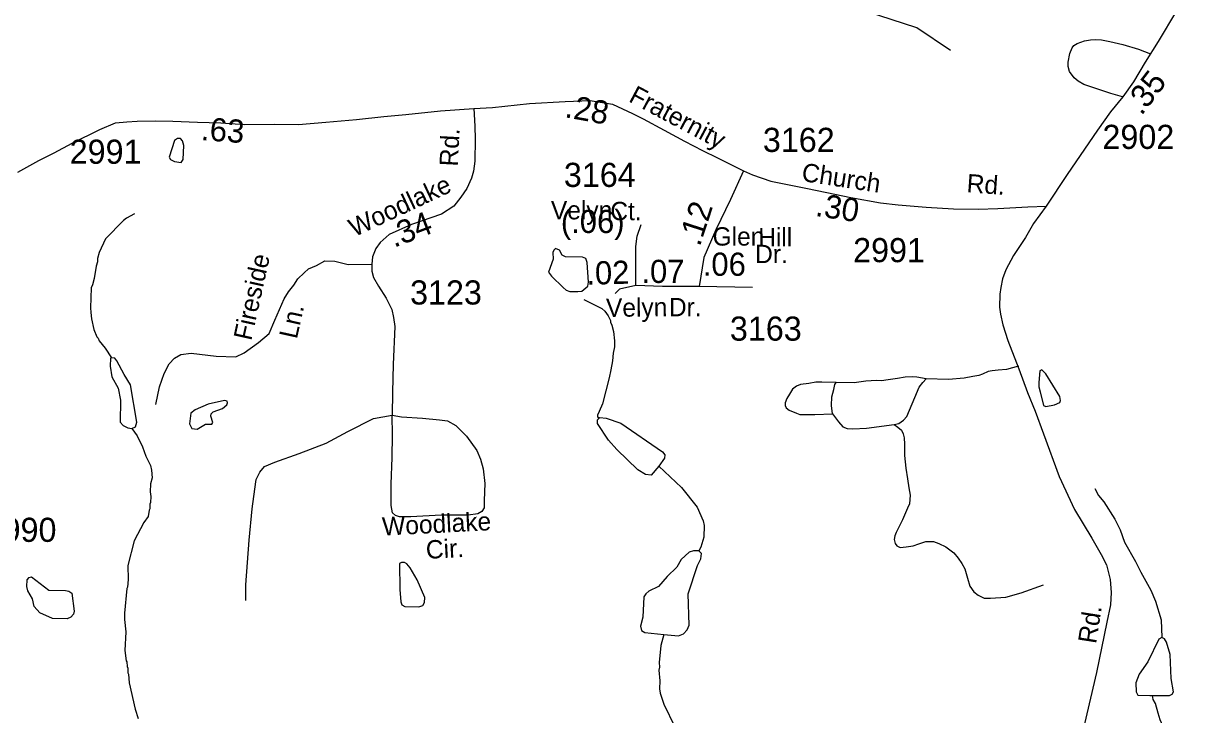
# Model space of a CAD drawing. Extents: x 1547597 to 1699558, y 810033 to 920809.
# Drawn here: x 1609618 to 1615688, y 824418 to 827999 of the extents above; entities that cross this region are included whole.
import ezdxf

# ---------------------------------------------------------------- set-up
doc = ezdxf.new("R2010")
doc.units = 0
for name, color, linetype in [('Exist Hydrographic Creek Single Shore', 7, 'Continuous'), ('Exist Hydrographic Misc Water Feature', 7, 'Continuous'), ('Exist Road Non-System Type 51', 7, 'Continuous'), ('Exist Road Non-System Type 51 Label', 7, 'Continuous'), ('Exist Road Secondary Mileage Hundredths English Label', 7, 'Continuous'), ('Exist Road Secondary Type 51 Attributed', 7, 'Continuous'), ('Exist Road Secondary Type 51 Label', 7, 'Continuous'), ('Exist Road Secondary Type 51 Number Label', 7, 'Continuous')]:
    doc.layers.add(name, color=color, linetype=linetype)

msp = doc.modelspace()

# ---------------------------------------------------------------- linework, layer by layer
at = {"layer": 'Exist Hydrographic Creek Single Shore'}
msp.add_lwpolyline([(1614418.7, 827857.8), (1614244.7, 827976.2), (1613920.7, 828081.3), (1613280.7, 828215.7), (1612876.7, 828552.1), (1612271.7, 828810.6), (1612074.7, 829021.4), (1611787.7, 829391.6), (1611415.7, 829665), (1611042.6, 829820.4), (1610759.7, 829865.5), (1610619.7, 829934), (1610330.7, 830205.7), (1610132.7, 830308.2), (1609659.7, 830472.1)], dxfattribs=at)
at = {"layer": 'Exist Hydrographic Misc Water Feature'}
for points in [[(1610448.8, 827365.8), (1610442.1, 827390), (1610431.1, 827402.6), (1610415.4, 827403.3), (1610400.9, 827392.8), (1610372.6, 827306.5), (1610379.9, 827293.4), (1610399.7, 827283), (1610434.4, 827278), (1610445.6, 827294.1), (1610448.8, 827365.8)], [(1610193, 827011.4), (1610150.8, 826990), (1610136.6, 826978.2), (1610043.4, 826883.5), (1610010.4, 826812), (1610002, 826780.2), (1610001.8, 826764.2), (1609993.5, 826740.3), (1609984.6, 826676.4), (1609976.2, 826644.6), (1609968, 826628.7), (1609964.6, 826524.7), (1609966.2, 826500.7), (1609969.8, 826468.7), (1609983, 826412.5), (1609998.5, 826374.3), (1610004.4, 826368.2), (1610010.2, 826354.2), (1610041.7, 826315.7), (1610073, 826266.8)], [(1612412.2, 826630.3), (1612429.1, 826616.3), (1612448.3, 826609.4), (1612488.6, 826609.5), (1612509.6, 826612.1), (1612540.1, 826638.2), (1612543.6, 826658.6), (1612537.1, 826759.6), (1612530.1, 826780.1), (1612513.1, 826788), (1612425.5, 826790.1), (1612408.5, 826798), (1612393.3, 826824.1), (1612374.1, 826832.1), (1612364.1, 826823.9), (1612360.1, 826811.3), (1612360.8, 826778.2), (1612336.9, 826710.6), (1612352.1, 826689.4), (1612412.2, 826630.3)], [(1612519.6, 826569.1), (1612612.9, 826521.8), (1612628.7, 826507.6), (1612646.4, 826483.3), (1612658, 826459.2), (1612657.9, 826451.2), (1612665.7, 826435.1), (1612673.3, 826403), (1612678.7, 826354.9), (1612678.2, 826322.9), (1612671.8, 826291.1), (1612669.2, 826251.1), (1612660.6, 826203.2), (1612652, 826163.4), (1612616.2, 826027.9), (1612599.7, 825988.1), (1612591.3, 825968.3), (1612591.2, 825960), (1612597.3, 825951.1)], [(1610073, 826266.8), (1610067.8, 826264.9), (1610066.7, 826223.4), (1610075.2, 826167.8), (1610108.3, 826108.3), (1610121, 826047), (1610119.1, 825933.7), (1610133.7, 825916), (1610158.2, 825903.1), (1610179, 825900.6)], [(1610179, 825900.6), (1610198.2, 825909), (1610204.1, 825932.1), (1610172.5, 826126.5), (1610138.7, 826180.4), (1610101.5, 826251.1), (1610091.1, 826263.9), (1610073, 826266.8)], [(1614883.3, 826090.7), (1614901.3, 826018.7), (1614912.1, 826014.1), (1614957, 826023.4), (1614984.5, 826034.8), (1614988.2, 826044.6), (1614985.3, 826065.7), (1614912.1, 826184.1), (1614891.7, 826204.6), (1614881.3, 826198.8), (1614875.8, 826139.2), (1614875.9, 826115.9), (1614883.3, 826090.7)], [(1610574.2, 826025.7), (1610506.7, 825996.3), (1610485.1, 825979.6), (1610477.7, 825924.9), (1610490.6, 825900.1), (1610517.1, 825897), (1610559.8, 825922.2), (1610592.7, 825922.7), (1610598.2, 825930.9), (1610587.6, 825964.3), (1610590, 825975.7), (1610600.2, 825987), (1610649.3, 826003.8), (1610670.4, 826023.2), (1610675.1, 826033.2), (1610672.4, 826041), (1610658.8, 826045.2), (1610574.2, 826025.7)], [(1612908.3, 825704.6), (1612868.3, 825657.6), (1612839.4, 825662.4), (1612799.2, 825686.5), (1612691.6, 825790.5), (1612648.2, 825840.1), (1612590.4, 825925.1), (1612590.6, 825944.5), (1612597.3, 825951.1)], [(1612597.3, 825951.1), (1612603, 825956.6), (1612636.3, 825953.6), (1612711.5, 825927.3), (1612926.7, 825779.9), (1612938.8, 825764), (1612938.6, 825745.6), (1612908.3, 825704.6)], [(1610179, 825900.6), (1610207.4, 825861.5), (1610234.5, 825805.1), (1610251.9, 825756.9), (1610275.2, 825708.6), (1610280.9, 825684.5), (1610284.4, 825644.5), (1610276, 825612.6), (1610273.4, 825572.7), (1610277.1, 825548.6), (1610276.6, 825516.6), (1610272.5, 825508.7), (1610272.2, 825484.7), (1610268.1, 825476.7), (1610263.7, 825444.8), (1610241.2, 825413.1), (1610192, 825317.9), (1610158.3, 825190.3), (1610159.3, 825118.4), (1610156.7, 825078.4), (1610152.6, 825070.5), (1610140.8, 824942.6), (1610140.4, 824910.6), (1610147.5, 824846.6), (1610142.3, 824750.7), (1610149.4, 824696.6), (1610153.4, 824690.5), (1610155.1, 824666.5), (1610159, 824658.5), (1610158.7, 824634.5), (1610162.6, 824626.4), (1610165.9, 824582.4), (1610196.1, 824446), (1610211.4, 824397.8)], [(1612908.3, 825704.6), (1613025.6, 825594.4), (1613107.8, 825492.4), (1613138.7, 825421.8), (1613143.7, 825398), (1613142.2, 825337.5), (1613126.7, 825285.8), (1613115, 825265.8)], [(1615166.7, 825589.1), (1615186.2, 825552.1), (1615213.7, 825519.7), (1615270.5, 825431), (1615297.7, 825374.6), (1615320.9, 825310.3), (1615376.9, 825211.5), (1615404.1, 825156.5)], [(1613115, 825265.8), (1613087.8, 825267), (1613065, 825258.5), (1613025, 825221.1), (1613000.9, 825181), (1612951.3, 825134.1), (1612905.9, 825082), (1612856.4, 825057.9), (1612841.4, 825044), (1612830.7, 825028.3), (1612826.1, 824923), (1612814.1, 824876.6), (1612818.3, 824853.7), (1612835.7, 824843), (1612934.2, 824833.5)], [(1612934.2, 824833.5), (1613011, 824826.1), (1613036.7, 824836.3), (1613055.2, 824856.3), (1613066.1, 824881.7), (1613060, 825043.3), (1613108, 825189.5), (1613126, 825224.4), (1613129, 825251.6), (1613115, 825265.8)], [(1611657.7, 825116.5), (1611621.1, 825177.5), (1611603.3, 825198.1), (1611591.7, 825206.4), (1611574.9, 825206.6), (1611566, 825201.4), (1611566.4, 825066.2), (1611572, 825001.5), (1611577.7, 824986.9), (1611592.2, 824978), (1611666.1, 824976), (1611685.9, 824982.8), (1611694.8, 824998.4), (1611695.7, 825024.6), (1611657.7, 825116.5)], [(1609767.9, 824916), (1609703, 824944.5), (1609673.5, 824977.4), (1609664.2, 825017.8), (1609640.4, 825059.8), (1609635.8, 825081.3), (1609636.2, 825116.8), (1609646.7, 825128.5), (1609659.9, 825131.8), (1609749.4, 825062), (1609835.4, 825060.3), (1609852.7, 825057.4), (1609868.6, 825046.1), (1609880.8, 824954.3), (1609876.4, 824937.7), (1609863.1, 824923.2), (1609844.2, 824913.7), (1609767.9, 824916)], [(1615404.1, 825156.5), (1615456.8, 825062.6), (1615480.7, 825005.2), (1615510.9, 824908.2), (1615514, 824816.9)], [(1612934.2, 824833.5), (1612919, 824776), (1612909.7, 824688.1), (1612911.4, 824664.1), (1612909.2, 824648.1), (1612914.5, 824592), (1612911.9, 824552.1), (1612915.6, 824528.1), (1612934.8, 824471.8), (1612991.2, 824355.1), (1613014.6, 824314.7), (1613070.7, 824178), (1613103.8, 824117.5), (1613115.4, 824085.4), (1613162.1, 823992.7), (1613191.1, 823920.3), (1613206.5, 823872.2), (1613217.7, 823824), (1613221.3, 823792), (1613225.2, 823783.9), (1613224.6, 823735.9), (1613239.6, 823663.8), (1613241.5, 823605.4)], [(1615514, 824816.9), (1615498.6, 824807.9), (1615440.8, 824691.4), (1615396.6, 824626.6), (1615379.8, 824582.5), (1615380, 824536.2), (1615389.3, 824519.1), (1615451.2, 824517.2), (1615464.6, 824517.2)], [(1615464.6, 824517.2), (1615553.9, 824516.6), (1615566.3, 824523.2), (1615574.6, 824536.1), (1615562.4, 824605), (1615556.3, 824729.6), (1615537.2, 824792.5), (1615527.2, 824809.6), (1615514, 824816.9)], [(1615494.3, 824424.5), (1615480, 824475.6), (1615468, 824496.7), (1615464.6, 824517.2)], [(1615297.7, 823552.8), (1615323.5, 823602.7), (1615331.6, 823610.6), (1615360.2, 823658.2), (1615380.5, 823681.9), (1615392.8, 823705.7), (1615498.7, 823848.2), (1615531.5, 823911.7), (1615535.9, 823927.7), (1615533.9, 823935.7), (1615540.1, 823943.6), (1615557.2, 824031.3), (1615572, 824091.1), (1615576.2, 824107), (1615576.9, 824155), (1615569.7, 824211.1), (1615550.5, 824275.4), (1615538.9, 824299.5), (1615523.5, 824347.7), (1615504.4, 824390.3), (1615494.3, 824424.5)]]:
    msp.add_lwpolyline(points, dxfattribs=at)
at = {"layer": 'Exist Road Non-System Type 51'}
for points in [[(1615310.7, 827617.8), (1615249.6, 827635), (1615110.3, 827682.6), (1615079.8, 827699.8), (1615059, 827717.3), (1615035.4, 827749.6), (1615028.1, 827774.9), (1615028, 827797.8), (1615036.5, 827843.6), (1615049.3, 827872.2), (1615058.5, 827883.8), (1615075.2, 827895), (1615113.3, 827908.5), (1615144.4, 827913.9), (1615169.2, 827915.8), (1615201.8, 827913.3), (1615245.1, 827904.8), (1615310.8, 827890.1), (1615392.3, 827865), (1615454.3, 827840.6)], [(1610302.5, 826024.8), (1610321.6, 826116.4), (1610346.6, 826184.2), (1610373, 826235.7), (1610399.4, 826265.3), (1610433.6, 826282.8), (1610485.6, 826290.2), (1610615.3, 826275.1), (1610717, 826271.2), (1610760.8, 826291.7), (1610834.5, 826345.9), (1610890, 826391.6), (1610920.2, 826461.4), (1610968.1, 826572.3), (1610990.1, 826607.5), (1611017.5, 826643.1), (1611038.1, 826675.5), (1611072.3, 826707), (1611093.8, 826726.7), (1611134.9, 826744.5), (1611179, 826768.3), (1611231.1, 826766.9), (1611299.5, 826750.4), (1611421.6, 826750.9)], [(1614770.8, 826223.8), (1614709.8, 826206.1), (1614665.1, 826202.1), (1614634.8, 826199.4), (1614613.3, 826194.7), (1614584.4, 826181.3), (1614566.4, 826174.8), (1614534.2, 826168.6), (1614489.5, 826161), (1614409.2, 826154.5), (1614293.6, 826158)], [(1614293.6, 826158), (1614244, 826166.6), (1614222.7, 826167.2), (1614183.5, 826166.6), (1614144.1, 826158.9), (1614095.8, 826151.4), (1614061.8, 826147.1), (1614035.2, 826147.9), (1613979.9, 826146), (1613920.9, 826137.1), (1613826.6, 826138.1)], [(1614128, 825920.7), (1614151.3, 825925.4), (1614175, 825942.5), (1614193.3, 825961.5), (1614206.8, 825994.9), (1614233.7, 826060), (1614256.7, 826114.6), (1614275.2, 826138.9), (1614293.6, 826158)], [(1613826.6, 826138.1), (1613751.9, 826140.4), (1613721.6, 826139.5), (1613685.8, 826133.5), (1613642.9, 826127.6), (1613621.3, 826119.4), (1613601.3, 826103.9), (1613584.5, 826077.7), (1613571.4, 826054.9), (1613563.6, 826033.8), (1613563.2, 826019.6), (1613568.1, 826007), (1613583.8, 825995.8), (1613620.7, 825978.7), (1613638.3, 825972.8), (1613661.4, 825972.1), (1613716.6, 825972.2), (1613807.5, 825976.6)], [(1613807.5, 825976.6), (1613803.5, 826019.5), (1613804.8, 826064), (1613814.9, 826102.9), (1613819.2, 826127.7), (1613826.6, 826138.1)], [(1610768.8, 825009.3), (1610769.8, 825089.4), (1610786.7, 825321), (1610802.8, 825484.7), (1610816.1, 825586.5), (1610822.7, 825636.4), (1610841.3, 825674), (1610865.7, 825703.8), (1610919.8, 825725.1), (1611046.2, 825771.3), (1611184.7, 825823.6), (1611297.4, 825884.1), (1611430.2, 825952.5), (1611528.2, 825969.1)], [(1611528.2, 825969.1), (1611576.1, 825960.5), (1611683.8, 825953.1), (1611771.7, 825944.1), (1611813.6, 825939.5), (1611857.1, 825915), (1611912.4, 825860.4), (1611965.3, 825785.7), (1611984.9, 825741.5), (1611998, 825691.4), (1612007.1, 825615.2), (1612003.9, 825527.4), (1612003.6, 825489.4), (1611991.1, 825469.6), (1611971.1, 825457.8), (1611921.1, 825450.4), (1611781.2, 825450.3), (1611623.4, 825442.3), (1611565.4, 825443), (1611545.1, 825449.4), (1611529.8, 825463.4), (1611522.1, 825501.5), (1611521.6, 825611.4), (1611527.4, 825749.4), (1611528.9, 825865.2), (1611528.2, 825969.1)], [(1613807.5, 825976.6), (1613838.3, 825934.7), (1613860.7, 825909.1), (1613883.5, 825899.5), (1613913.8, 825898.6), (1613983.3, 825901.9), (1614128, 825920.7)], [(1614128, 825920.7), (1614145.5, 825907.7), (1614164.5, 825891.1), (1614174.7, 825873), (1614179.4, 825851.5), (1614180.2, 825819.4), (1614180.2, 825760.6), (1614187.1, 825694.5), (1614196.2, 825639.4), (1614203.7, 825592.9), (1614209.7, 825555.3), (1614209, 825532.1), (1614206.5, 825509.1), (1614197, 825488), (1614170.2, 825426.4), (1614151.3, 825389.6), (1614138, 825361.5), (1614130.3, 825343.9), (1614128, 825324.4), (1614132.7, 825304.7), (1614141.2, 825291.9), (1614158.8, 825284.3), (1614189.2, 825286.9), (1614224.9, 825293), (1614255.5, 825302.8), (1614291.4, 825314.2), (1614330.6, 825314.8), (1614358.8, 825305), (1614395.6, 825286.1), (1614435.6, 825255.7), (1614458, 825228.3), (1614478.5, 825201), (1614493.7, 825173.8), (1614506.5, 825125.3), (1614519.5, 825084), (1614539.9, 825053.1), (1614562.6, 825036.4), (1614594.2, 825021.2), (1614626.2, 825020.2), (1614706.5, 825026.7)], [(1614706.5, 825026.7), (1614785.1, 825049.3), (1614900.3, 825090.4)]]:
    msp.add_lwpolyline(points, dxfattribs=at)
at = {"layer": 'Exist Road Secondary Type 51 Attributed'}
msp.add_line((1613394.2, 826631.3), (1613118.2, 826635.5), dxfattribs=at)
for points in [[(1615872.1, 828613.9), (1615854.5, 828536.3), (1615829.8, 828455.1), (1615794.5, 828359.8), (1615745.1, 828261), (1615678.1, 828169.2), (1615589.9, 828063.3), (1615494.7, 827904.5), (1615427.7, 827798.6), (1615367.7, 827696.2), (1615311.3, 827618.6), (1615247.8, 827540.9), (1615180.8, 827445.6), (1615022.9, 827216.6), (1614915.3, 827052.5)], [(1609589.3, 827228), (1609698.1, 827287.9), (1609777, 827328.7), (1609869.5, 827377.7), (1610013.7, 827448.5), (1610095.3, 827483.9), (1610152.4, 827489.3), (1610206.8, 827492), (1610299.3, 827494.8), (1610391.8, 827492), (1610519.6, 827486.6), (1610639.3, 827483.9), (1610764.4, 827475.7), (1610916.7, 827476.1), (1611042.5, 827474.6), (1611184.4, 827486.7), (1611342.4, 827500.7), (1611484.2, 827516.5), (1611598.9, 827526.9), (1611777, 827545.5), (1611950.9, 827558.1)], [(1611950.9, 827558.1), (1611955.9, 827466.1), (1611956.8, 827398.6), (1611955.9, 827284.6), (1611949.2, 827234), (1611938.2, 827196.8), (1611914.6, 827142.8), (1611882.5, 827098.9), (1611847, 827052.5), (1611783.7, 827010.7), (1611627.4, 826956.5), (1611511.1, 826904.5), (1611480.6, 826878.2), (1611464.7, 826864.1), (1611443.5, 826832.3), (1611425.1, 826790), (1611421.6, 826750.9), (1611421.6, 826714.9), (1611430.9, 826682), (1611456.2, 826638.1), (1611496.9, 826574.5), (1611526.3, 826515.9), (1611534.7, 826474.7), (1611540.6, 826428.3), (1611532.8, 826231.6), (1611529.5, 826087.9), (1611528.2, 825969.1)], [(1611950.9, 827558.1), (1612046.3, 827563), (1612238.7, 827584.3), (1612423.8, 827594.8), (1612552.2, 827599.2), (1612668.6, 827580.2), (1612772.5, 827531.4), (1612828.2, 827505.1), (1612936, 827444.9), (1613041, 827389.2), (1613134.3, 827340.1), (1613212.8, 827302.8), (1613347.8, 827235.3)], [(1613347.8, 827235.3), (1613279.4, 827086.7), (1613203.5, 826928.9), (1613141.4, 826785.8), (1613118.2, 826635.5)], [(1613347.8, 827235.3), (1613393.4, 827215), (1613488.8, 827182.1), (1613678.7, 827144.1), (1613820.5, 827113.7), (1613903.2, 827097.7), (1614056, 827069.4), (1614148.8, 827058.4), (1614292.3, 827047.4), (1614434.1, 827037.3), (1614561.6, 827035.6), (1614663.7, 827040.7), (1614819.9, 827048.3), (1614915.3, 827052.5)], [(1614915.3, 827052.5), (1614849, 826963), (1614808.1, 826889.6), (1614745.6, 826797.2), (1614705.1, 826722.9), (1614689, 826674.8), (1614680.6, 826630.9), (1614673.9, 826595.4), (1614673, 826529.2), (1614677.2, 826492), (1614689.9, 826437.2), (1614715.8, 826355.9), (1614773.6, 826209.8), (1614818, 826087.3), (1614857, 825989), (1614900.9, 825871.6), (1614982.7, 825651.6), (1615061.6, 825480.4), (1615151.9, 825332.3), (1615200, 825247.7), (1615226.9, 825193.8), (1615246.1, 825117.8), (1615252, 825049.5), (1615247, 824987), (1615229.3, 824896.7), (1615175.2, 824635.9), (1615112.8, 824369.6)], [(1612789, 826641.4), (1612789, 826842.2), (1612795.8, 826897.2), (1612816.9, 826957.1)], [(1612789, 826641.4), (1612705.5, 826621.2), (1612681.8, 826599.2)], [(1613118.2, 826635.5), (1612927.9, 826635), (1612789, 826641.4)]]:
    msp.add_lwpolyline(points, dxfattribs=at)

# ---------------------------------------------------------------- texts
at = {"layer": 'Exist Road Non-System Type 51 Label'}
for s, rotation, p in [('Fireside', 77.52845, (1610797.4, 826351.7)), ('Ln.', 77.52845, (1611033.6, 826360.3)), ('Woodlake', 2.90327, (1611477.8, 825344.8)), ('Cir.', 2.90327, (1611704.3, 825224.5))]:
    msp.add_text(s, height=95, rotation=rotation, dxfattribs=at).set_placement(p)
at = {"layer": 'Exist Road Secondary Mileage Hundredths English Label'}
for s, rotation, p in [('.35', 52.57691, (1615408, 827517.4)), ('.28', 349.84069, (1612417.2, 827513.4)), ('.63', 355.8879, (1610534.8, 827394.2)), ('.12', 71.80171, (1613120.3, 826839.1)), ('.30', 351.31687, (1613715.2, 827002)), ('.34', 21.11238, (1611537.3, 826836)), ('(.06)', 359.928, (1612401, 826913.1)), ('.02', 1.48981, (1612534.6, 826644.6)), ('.07', 0.09789, (1612818.2, 826653.9))]:
    msp.add_text(s, height=120, rotation=rotation, dxfattribs=at).set_placement(p)
msp.add_text('.06', height=120, dxfattribs=at).set_placement((1613136, 826691.3))
at = {"layer": 'Exist Road Secondary Type 51 Label'}
for s, rotation, p in [('Fraternity', 332.03313, (1612747.2, 827596.7)), ('Rd.', 87.02819, (1611866.8, 827256.1)), ('Church', 351.23032, (1613644, 827183.3)), ('Woodlake', 25.08, (1611331.2, 826890.9)), ('Rd.', 356.01133, (1614500.7, 827124.3)), ('Velyn', 0.76643, (1612635.4, 826477.9)), ('Rd.', 81.10903, (1615172.7, 824781.6))]:
    msp.add_text(s, height=95, rotation=rotation, dxfattribs=at).set_placement(p)
for s, p in [('Velyn', (1612349.5, 826983.6)), ('Ct.', (1612657.3, 826979.3)), ('Glen', (1613186.8, 826847.7)), ('Hill', (1613422.9, 826843.4)), ('Dr.', (1613407.1, 826756.9)), ('Dr.', (1612960.6, 826481.5))]:
    msp.add_text(s, height=95, dxfattribs=at).set_placement(p)
at = {"layer": 'Exist Road Secondary Type 51 Number Label'}
for s, p in [('3162', (1613447.3, 827333)), ('2902', (1615206.1, 827348.5)), ('2991', (1609857.2, 827271.6)), ('3164', (1612416.7, 827151.6)), ('2991', (1613914.9, 826761.7)), ('3123', (1611620.1, 826542.4)), ('3163', (1613276.6, 826355.1)), ('2990', (1609416.9, 825312.7))]:
    msp.add_text(s, height=125, dxfattribs=at).set_placement(p)

doc.saveas('drawing.dxf')
